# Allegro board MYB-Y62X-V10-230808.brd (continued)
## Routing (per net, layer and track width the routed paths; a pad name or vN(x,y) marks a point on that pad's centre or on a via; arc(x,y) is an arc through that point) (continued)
SOC_MCU_MCAN1_TX: length 60.2
  TOP w0.152: v2(45.44,112.07) R77.2 45.77,110.16 U47.15 ; U43.L56 76.12,89.79 v2(75.48,90.42)
  BOTTOM w0.152: v2(75.48,90.42) 75.21,90.7 70,90.7 65.4,95.3 61.79,95.3 57.91,99.19 43.61,99.19 41.07,101.73 41.07,109.73 43.41,112.07 v2(45.44,112.07)
SOC_MCU_RESETZ: length 119.8
  TOP w0.152: v2(160.07,14.99) 160.07,14.25 160.45,13.87 D44.1 ; v2(81.23,47.42) 81.23,49.76 U43.L21
  ART03 w0.152: v2(160.07,14.99) 160.07,16.89 158.92,18.03 155.11,18.03 v2(154.15,19)
  BOTTOM w0.152: C240.1 R414.2 160.83,14.22 v2(160.07,14.99) ; v2(81.23,47.42) 85.42,47.42 86.64,48.64 90.93,48.64 91.39,48.18 105.18,48.18 109.67,52.68 110.54,52.68 111.02,52.2 114.5,52.2 116.05,50.65 116.05,45.9 117.56,44.39 122.51,44.39 124.63,42.27 124.63,27.33 125.04,26.92 126.44,26.92 127.05,26.31 127.05,24.21 127.5,23.75 137.94,23.75 138.43,24.23 140.23,24.23 140.51,24.51 144.47,24.51 145.73,23.25 148.42,23.25 150.08,21.59 150.9,21.59 151.18,21.31 151.18,20.02 151.41,19.79 152.08,19.79 152.86,19 v2(154.15,19)
SOC_MCU_SPI0_CLK: length 87.6
  TOP w0.152: U18.8 158.4,70.22 158.67,70.48 R158.2 159.37,70.97 159.22,71.12 152.95,71.12 152.07,72.01 150.67,72.01 148.64,74.04 v2(143.38,74.04) ; U43.L53 v2(82.72,87.88)
  ART03 w0.152: v2(102.47,87.3) 102.42,87.25 83.36,87.25 v2(82.72,87.88)
  BOTTOM w0.152: v2(143.38,74.04) 143.38,75.16 138.27,80.26 132.71,80.26 132.3,80.67 120.16,80.67 115.41,85.42 105.61,85.42 103.73,87.3 v2(102.47,87.3)
SOC_MCU_SPI0_CS0: length 101.5
  TOP w0.152: U43.L2 68.5,84.71 v2(67.99,84.2) ; v2(119.55,83.31) 121.08,81.79 128.22,81.79 128.9,81.1 128.9,79.15 129.94,78.11 137.97,78.11 142.54,73.53 148.38,73.53 150.54,71.37 151.87,71.37 R159.2 153.03,70.22 U18.1
  ART03 w0.152: v2(67.99,84.2) 67.99,86.74 70.28,89.03 79,89.03 79.93,89.96 98.23,89.96 98.42,90.14 103.7,90.14 110.16,83.69 117.14,83.69 117.52,83.31 v2(119.55,83.31)
SOC_MCU_SPI0_D0: length 140.2
  TOP w0.152: U43.L3 66.72,82.8 v2(65.83,81.92)
  ART03 w0.152: v2(65.83,81.92) 65.22,82.52 65.22,87.68 70.89,93.34 91.61,93.34 92.63,92.33 94.53,92.33 95.14,91.72 104.8,91.72 110.79,85.72 118.16,85.72 118.66,85.22 v2(120.06,85.22)
  BOTTOM w0.152: v2(120.06,85.22) 120.06,85.06 122.42,82.7 137.82,82.7 145.21,75.31 145.21,60.12 152.41,52.92 152.41,50.71 159.18,43.94 161.59,43.94 161.78,43.76 R160.2 R148.2
SOC_MCU_SPI0_D1: length 63.4
  TOP w0.152: R127.2 v2(16.3,94.36) ; U43.L4 v2(65.83,80.26)
  ART03 w0.152: v2(50.24,89.99) 50.72,89.51 v2(50.72,81.81)
  BOTTOM w0.152: v2(65.83,80.26) 64.28,81.81 v2(50.72,81.81) ; v2(50.24,89.99) 49.95,90.28 31.61,90.28 27.53,94.36 v2(16.3,94.36)
SOC_MCU_UART0_RXD: length 77.5
  TOP w0.152: U43.L1 v2(68.5,86.23) ; R12.1 79.55,27.84 78.53,28.85 v2(69.24,28.85)
  BOTTOM w0.152: v2(68.5,86.23) 68.75,85.98 68.75,83.82 67.46,82.52 67.46,74.45 68.75,73.15 68.75,59.31 66.85,57.4 66.85,45.21 62.73,41.1 62.73,35.36 v2(69.24,28.85)
SOC_MCU_UART0_TXD: length 82.6
  TOP w0.152: v2(79.57,21.21) R562.1 ; U43.L58 69.77,87.88 69.13,87.25 v2(69.13,86.74)
  BOTTOM w0.152: v2(79.57,21.21) 77.19,21.21 72.61,25.78 71.59,25.78 62.23,35.15 62.23,41.31 66.34,45.42 66.34,57.61 68.25,59.52 68.25,72.94 66.95,74.24 66.95,83.92 67.99,84.96 67.99,86.36 68.37,86.74 v2(69.13,86.74)
SOC_MMC1_CLK: length 31.6
  TOP w0.152: J2.5 81.22,109.89 82.22,108.89 D5.2 82.19,108.09 81.56,107.46 81.56,106.2 82.09,105.66 v2(82.22,105.66) R37.2 ; U43.149 81.78,92.51 81.1,93.19 78.96,93.19 78.81,93.34 v2(78.81,94.23)
  BOTTOM w0.152: v2(82.22,105.66) 82.22,105.79 82.7,106.27 82.7,106.6 83.1,107.01 84.68,107.01 85.01,106.68 85.01,105.54 81.81,102.34 81.81,99.31 80.95,98.45 80.95,95.83 79.35,94.23 v2(78.81,94.23)
SOC_MMC1_CMD: length 32
  TOP w0.152: U43.156 v2(74.78,94.35) ; J2.3 79.02,108.11 D4.2 79.55,107.58 79.55,106.17 v2(79.04,105.66) R36.2
  BOTTOM w0.152: v2(79.04,105.66) 77.95,104.57 77.95,104.13 78.08,104 78.32,104 78.46,103.86 78.46,103.67 78.32,103.54 78.08,103.54 77.95,103.41 77.95,102.95 75.09,100.09 75.09,98.66 74.95,98.53 74.72,98.53 74.57,98.68 74.57,99.26 74.42,99.42 73.35,99.42 73.2,99.26 73.2,98.99 73.35,98.84 73.83,98.84 73.99,98.69 73.99,98.38 73.83,98.23 73.35,98.23 73.2,98.08 73.2,97.75 73.35,97.59 73.83,97.59 73.99,97.44 73.99,97.14 73.83,96.98 73.61,96.98 73.4,96.77 73.4,96.47 73.63,96.24 75.36,96.24 75.51,96.09 75.51,95.76 75.36,95.61 74.37,95.61 74.21,95.45 74.21,94.87 74.73,94.35 v2(74.78,94.35)
SOC_MMC1_DAT0: length 31.3
  TOP w0.152: v2(75.78,94.35) 75.43,94.35 75.28,94.2 75.28,93.7 75.43,93.55 75.63,93.55 75.78,93.39 U43.155 ; R38.2 v2(83.36,105.66) 83.36,105.66 82.75,106.27 82.75,107.48 D6.2 83.42,108.15 J2.7
  BOTTOM w0.152: v2(83.36,105.66) 83.36,105.49 82.17,104.29 81.46,104.29 81.3,104.44 81.3,104.98 81.15,105.13 80.85,105.13 80.69,104.98 80.69,104.44 80.54,104.29 80.01,104.29 79.6,103.89 79.6,102.64 79.45,102.49 78.1,102.49 77.89,102.27 77.89,102.06 78.04,101.9 79.52,101.9 79.63,101.8 79.63,98.09 78.13,96.6 78.13,95.38 77.87,95.12 76.88,95.12 76.11,94.35 v2(75.78,94.35)
SOC_MMC1_DAT1: length 31.8
  TOP w0.152: J2.8 84.52,108.1 D7.2 83.87,107.45 83.87,105.74 v2(83.94,105.66) 84.01,105.66 R39.2 ; v2(76.78,94.36) 76.4,94.36 76.25,94.21 76.25,93.85 76.4,93.69 77.29,93.69 77.44,93.54 77.44,93.24 77.29,93.08 76.4,93.08 76.25,92.93 76.25,92.61 76.4,92.46 76.67,92.46 76.78,92.35 U43.154
  BOTTOM w0.152: v2(76.78,94.36) 76.78,94.39 77.14,94.74 78,94.74 78.46,95.2 78.46,96.32 79.14,97 79.36,97 79.5,96.86 79.72,96.86 79.93,97.08 79.93,97.3 79.79,97.44 79.79,97.65 80.08,97.94 80.08,100.06 80.23,100.21 80.77,100.21 80.92,100.36 80.92,100.67 80.77,100.82 80.23,100.82 80.08,100.97 80.08,101.27 80.23,101.43 80.77,101.43 80.92,101.58 80.92,101.88 80.77,102.04 80.23,102.04 80.08,102.19 80.08,103.61 80.31,103.84 82.27,103.84 83.94,105.51 v2(83.94,105.66)
SOC_MMC1_DAT2: length 31.4
  TOP w0.152: R34.2 v2(76.88,105.66) 77.39,106.17 77.39,107.58 D2.2 76.82,108.15 J2.1 ; U43.158 v2(72.78,94.35)
  BOTTOM w0.152: v2(72.78,94.35) 72.6,94.35 71.93,95.02 71.93,95.61 71.78,95.76 70.51,95.76 70.25,96.01 70.25,98.35 70.1,98.5 69.39,98.5 69.24,98.65 69.24,98.93 69.39,99.08 70.13,99.08 70.28,99.23 70.28,99.54 70.13,99.69 69.39,99.69 69.24,99.84 69.24,100.2 69.4,100.37 74.23,100.37 76.88,103.02 v2(76.88,105.66)
SOC_MMC1_DAT3: length 31.8
  TOP w0.152: U43.157 v2(73.78,94.35) ; J2.2 77.92,108.2 D3.2 78.53,107.58 78.53,106.17 v2(78.02,105.66) R35.2
  BOTTOM w0.152: v2(78.02,105.66) 77.39,105.03 77.39,102.97 74.34,99.92 71.09,99.92 70.94,99.77 70.94,99.55 71.07,99.42 72.54,99.42 72.69,99.26 72.69,99 72.56,98.87 72.27,98.87 72.13,98.73 72.13,98.55 72.27,98.41 72.56,98.41 72.69,98.28 72.69,98.08 72.54,97.93 72.24,97.93 72.11,97.8 72.11,96.9 71.95,96.75 71.05,96.75 70.91,96.62 70.91,96.34 71.04,96.22 72.77,96.22 73.78,95.2 v2(73.78,94.35)
SOC_MMC1_SDCD: length 32.7
  TOP w0.152: v2(71.95,94.34) 71.78,94.16 U43.159 ; R40.2 v2(85.99,105.64) 86.08,105.73 86.08,107.53 D8.2 85.62,108.19 J2.9
  BOTTOM w0.152: v2(85.99,105.64) 85.99,105.35 82.75,102.11 82.75,98.86 81.89,97.99 81.89,95.48 79.83,93.42 78.18,93.42 77.8,93.8 72.49,93.8 v2(71.95,94.34)
SOC_MMC2_CLK: length 58.2
  TOP w0.152: U43.144 86.78,92.08 v2(86.28,92.58) ; R85.1 v2(43.78,107.52)
  BOTTOM w0.152: v2(86.28,92.58) 86.03,92.33 84.5,92.33 84.02,92.81 82.57,92.81 81.53,91.77 79.98,91.77 79.52,91.31 77.06,91.31 76.81,91.57 70.53,91.57 65.6,96.49 62.05,96.49 58.21,100.33 43.64,100.33 41.96,102.01 41.96,105.7 v2(43.78,107.52)
SOC_MMC2_CMD: length 58.3
  TOP w0.152: R84.1 v2(43.23,108.41) ; U43.147 v2(83.78,92.33)
  BOTTOM w0.152: v2(83.78,92.33) 83.78,91.4 83.61,91.24 83.2,91.24 83.05,91.39 83.05,91.67 82.9,91.82 82.59,91.82 82.44,91.67 82.44,91.34 82.29,91.19 80.11,91.19 79.8,90.88 76.78,90.88 76.55,91.11 70.35,91.11 65.57,95.9 61.86,95.9 58.06,99.69 43.74,99.69 41.58,101.85 41.58,106.76 v2(43.23,108.41)
SOC_MMC2_DAT0: length 58.3
  TOP w0.152: R78.1 v2(43.61,104.14) ; U43.146 84.78,92.81 v2(84.76,92.84)
  BOTTOM w0.152: v2(43.61,104.14) 43.2,103.73 43.2,102.56 43.81,101.96 46.94,101.96 47.85,102.87 48.79,102.87 48.94,103.02 48.94,103.35 49.09,103.5 49.39,103.5 49.55,103.35 49.55,103.02 49.7,102.87 50,102.87 50.16,103.02 50.16,103.35 50.31,103.5 50.61,103.5 50.77,103.35 50.77,103.02 50.92,102.87 51.22,102.87 51.38,103.02 51.38,103.35 51.53,103.5 51.83,103.5 51.99,103.35 51.99,103.02 52.14,102.87 52.44,102.87 52.6,103.02 52.6,103.35 52.75,103.5 53.05,103.5 53.2,103.35 53.2,103.02 53.36,102.87 53.66,102.87 53.81,103.02 53.81,103.35 53.97,103.5 54.27,103.5 54.42,103.35 54.42,103.02 54.58,102.87 54.88,102.87 55.03,103.02 55.03,103.35 55.19,103.5 55.49,103.5 55.64,103.35 55.64,103.02 55.8,102.87 56.1,102.87 56.25,103.02 56.25,103.35 56.41,103.5 56.71,103.5 56.86,103.35 56.86,103.02 57.01,102.87 57.38,102.87 57.53,103.02 57.53,103.33 57.68,103.48 57.99,103.48 58.14,103.33 58.14,103.02 58.29,102.87 61.17,102.87 71.08,92.96 77.4,92.96 77.62,92.74 80.64,92.74 81.25,93.34 84.25,93.34 v2(84.76,92.84)
SOC_MMC2_DAT1: length 58.2
  TOP w0.152: R80.1 v2(43.61,103) ; v2(85.78,93.88) U43.145
  BOTTOM w0.152: v2(43.61,103) 44.17,102.44 45.64,102.44 47.14,103.94 47.89,103.94 48.04,104.09 48.04,104.55 48.19,104.7 48.5,104.7 48.65,104.55 48.65,104.11 48.83,103.94 49.11,103.94 49.26,104.09 49.26,104.55 49.41,104.7 49.72,104.7 49.87,104.55 49.87,104.11 50.05,103.94 50.33,103.94 50.48,104.09 50.48,104.55 50.63,104.7 50.93,104.7 51.09,104.55 51.09,104.11 51.26,103.94 51.54,103.94 51.7,104.09 51.7,104.55 51.85,104.7 52.15,104.7 52.31,104.55 52.31,104.11 52.48,103.94 52.76,103.94 52.92,104.09 52.92,104.55 53.07,104.7 53.37,104.7 53.53,104.55 53.53,104.11 53.7,103.94 54.27,103.94 54.43,104.09 54.43,104.5 54.58,104.65 54.88,104.65 55.04,104.5 55.04,104.09 55.19,103.94 60.8,103.94 71.41,93.33 77.61,93.33 77.87,93.07 80.16,93.07 80.95,93.85 85.75,93.85 v2(85.78,93.88)
SOC_MMC2_DAT2: length 57.9
  TOP w0.152: R82.1 v2(43.61,105.28) ; U43.153 v2(77.78,92.25)
  BOTTOM w0.152: v2(43.61,105.28) 42.72,104.39 42.72,102.62 43.89,101.45 48.54,101.45 48.69,101.6 48.69,102.16 48.84,102.31 49.15,102.31 49.3,102.16 49.3,101.6 49.45,101.45 49.76,101.45 49.91,101.6 49.91,102.16 50.06,102.31 50.37,102.31 50.52,102.16 50.52,101.6 50.67,101.45 50.98,101.45 51.13,101.6 51.13,102.16 51.28,102.31 51.59,102.31 51.74,102.16 51.74,101.6 51.89,101.45 52.2,101.45 52.35,101.6 52.35,102.16 52.5,102.31 52.81,102.31 52.96,102.16 52.96,101.6 53.11,101.45 53.42,101.45 53.57,101.6 53.57,102.16 53.72,102.31 54.03,102.31 54.18,102.16 54.18,101.6 54.33,101.45 54.64,101.45 54.79,101.6 54.79,102.16 54.94,102.31 55.25,102.31 55.4,102.16 55.4,101.6 55.55,101.45 55.86,101.45 56.01,101.6 56.01,102.16 56.16,102.31 56.46,102.31 56.62,102.16 56.62,101.6 56.77,101.45 57.07,101.45 57.23,101.6 57.23,102.16 57.38,102.31 57.68,102.31 57.84,102.16 57.84,101.6 57.99,101.45 58.29,101.45 58.45,101.6 58.45,102.16 58.6,102.31 58.9,102.31 59.06,102.16 59.06,101.6 59.21,101.45 59.51,101.45 59.67,101.6 59.67,102.11 59.82,102.26 60.12,102.26 60.27,102.11 60.27,101.6 60.43,101.45 61.82,101.45 70.76,92.51 77.19,92.51 77.44,92.25 v2(77.78,92.25)
SOC_MMC2_DAT3: length 57.9
  TOP w0.152: R83.1 v2(43.73,106.43) ; U43.151 v2(79.78,92.3)
  BOTTOM w0.152: v2(43.73,106.43) 42.34,105.03 42.34,102.36 43.76,100.94 58.37,100.94 59.57,99.74 59.79,99.74 60.6,100.55 60.81,100.55 61.03,100.33 61.03,100.12 60.27,99.35 60.27,99.04 60.48,98.82 60.7,98.82 61.51,99.63 61.73,99.63 61.94,99.42 61.94,99.2 61.13,98.39 61.13,98.18 61.35,97.96 61.56,97.96 62.3,98.7 62.51,98.7 62.73,98.48 62.73,98.26 61.99,97.53 61.99,97.31 62.32,96.99 63.48,96.99 63.63,97.14 63.63,98.02 63.78,98.17 64.09,98.17 64.24,98.02 64.24,97.14 64.39,96.99 65.74,96.99 70.66,92.08 77.01,92.08 77.34,91.74 79.22,91.74 v2(79.78,92.3)
SOC_MMC2_SDCD: length 100.2
  TOP w0.152: U43.148 v2(82.78,92.33) ; v2(60.31,21.34) R308.2 59.74,20.57 59.38,20.22 59.38,19.66 59.12,19.4 U29.6
  ART03 w0.152: v2(66.44,78.99) 66.44,82.12 65.76,82.8 65.76,87.5 70.05,91.8 78.96,91.8 79.32,92.15 79.32,92.53 79.63,92.84 81.38,92.84 81.88,92.33 v2(82.78,92.33)
  BOTTOM w0.152: v2(66.44,78.99) 66.44,74.07 67.74,72.77 67.74,59.82 65.83,57.91 65.83,47.75 64.74,46.66 59.41,46.66 57.58,44.83 57.58,40.77 56.18,39.37 56.18,31.17 58.21,29.13 58.21,25.4 58.85,24.77 58.85,23.11 60.31,21.65 v2(60.31,21.34)
SOC_OSPI0_CLK: length 11.2
  TOP w0.152: R51.2 v2(89.84,93.83) ; v2(97.71,92.46) 97.79,92.46 98.78,91.46 U43.132
  BOTTOM w0.152: v2(89.84,93.83) 89.84,93.73 90.19,93.37 91.77,93.37 93.01,92.13 95.47,92.13 96.06,92.71 97.46,92.71 v2(97.71,92.46)
SOC_OSPI0_CSN0: length 15.9
  TOP w0.152: R54.2 v2(90.72,93.83) ; v2(102.78,93.24) U43.128
  BOTTOM w0.152: v2(90.72,93.83) 91.92,93.83 93.21,92.53 95.3,92.53 95.88,93.12 96.47,93.12 97.15,93.8 102.22,93.8 v2(102.78,93.24)
SOC_OSPI0_CSN1: length 24.4
  TOP w0.152: U43.129 101.78,93.5 103.15,94.87 108.89,94.87 113.71,90.04 119.61,90.04 120.38,90.81 R285.1
SOC_OSPI0_DQ0: length 11.1
  TOP w0.152: v2(97.2,93.22) 97.2,94.18 R52.2 ; U43.139 v2(91.78,92.46)
  BOTTOM w0.152: v2(91.78,92.46) 92.54,91.69 97.71,91.69 98.22,92.2 98.22,92.71 97.71,93.22 v2(97.2,93.22)
SOC_OSPI0_DQ1: length 4.2
  TOP w0.152: R53.2 92.5,93.68 92.38,93.55 92.05,93.55 91.89,93.4 91.89,93.07 92.05,92.91 92.63,92.91 92.78,92.76 U43.138
SOC_OSPI0_DQ2: length 9.9
  TOP w0.152: U43.137 v2(93.78,90.37) ; R55.2 v2(99.61,93.22)
  BOTTOM w0.152: v2(93.78,90.37) 98.01,90.37 99.61,91.97 v2(99.61,93.22)
SOC_OSPI0_DQ3: length 12.4
  TOP w0.152: R56.2 98.34,93.92 v2(98.34,93.22) ; U43.140 v2(90.78,92.46)
  BOTTOM w0.152: v2(90.78,92.46) 91.92,91.31 97.84,91.31 98.6,92.08 98.6,92.96 v2(98.34,93.22)
SOC_OSPI0_DQ4: length 14
  TOP w0.152: R58.2 98.98,94.18 v2(98.98,93.22) ; U43.141 v2(89.78,92.46)
  BOTTOM w0.152: v2(98.98,93.22) 98.98,91.95 97.96,90.93 91.3,90.93 v2(89.78,92.46)
SOC_OSPI0_DQ5: length 3.8
  TOP w0.152: U43.133 97.78,91.6 96.74,92.63 96.74,93.74 R59.2
SOC_OSPI0_DQ6: length 4.7
  TOP w0.152: R60.2 92.91,93.95 92.91,93.37 93.24,93.04 93.24,92.41 93.42,92.23 94.58,92.23 94.78,92.02 U43.136
SOC_OSPI0_DQ7: length 21.2
  TOP w0.152: U43.142 88.78,92.06 87.25,93.6 87.25,97.18 87.4,97.33 87.89,97.33 88.14,97.08 88.99,97.08 89.12,96.94 89.12,96.76 88.99,96.62 88.14,96.62 88.01,96.49 88.01,96.3 88.14,96.16 88.99,96.16 89.12,96.03 89.12,95.84 88.99,95.71 88.14,95.71 88.01,95.57 88.01,95.38 88.14,95.25 88.99,95.25 89.12,95.12 89.12,94.93 88.99,94.79 88.14,94.79 88.01,94.66 88.01,93.9 88.67,93.24 91.03,93.24 91.61,93.83 R61.2
SOC_OSPI0_DQS: length 11.9
  TOP w0.152: U43.135 95.78,92.48 95.6,92.66 93.77,92.66 93.65,92.79 93.65,93.01 93.8,93.17 94.81,93.17 94.97,93.32 v2(94.97,93.7) 94.97,94.23 R63.1
  BOTTOM w0.152: v2(94.97,93.7) 94.97,93.55 94.81,93.4 93.55,93.4 93.4,93.24 93.4,93.06 93.52,92.94 95.12,92.94 95.58,93.4 95.58,94.02 R63.1
SOC_OSPI0_ECC_FAIL: length 3.4
  TOP w0.152: R57.2 100.15,94.07 100.15,92.74 99.78,92.37 U43.131
SOC_OSPI0_LBCLK: length 13.2
  TOP w0.152: U43.127 103.78,92.91 v2(102.82,93.88) ; v2(95.8,96.98) 95.8,96.82 95.17,96.19 R63.2
  BOTTOM w0.152: v2(95.8,96.98) 99.72,96.98 v2(102.82,93.88)
SOC_OSPI0_RESETOUT1: length 26.7
  TOP w0.152: U43.130 v2(100.78,92.31) ; v2(97.33,111.45) U8.1
  BOTTOM w0.152: v2(97.33,111.45) 97.89,110.89 97.89,102.44 99.87,100.46 99.87,97.66 103.35,94.18 103.35,93.17 102.49,92.31 v2(100.78,92.31)
SOC_PORZ_OUT: length 20.8
  TOP w0.152: v2(72.54,47.73) 74.06,47.73 U43.L19 ; U35.2 v2(70.74,38.1) 66.87,38.1 U39.2
  BOTTOM w0.152: v2(70.74,38.1) 70.74,45.92 v2(72.54,47.73)
SOC_RESET_REQZ: length 126.4
  TOP w0.152: D46.1 160.93,21.74 v2(160.7,21.97) ; U43.L17 v2(71.04,47.37)
  BOTTOM w0.152: C242.1 R416.2 v2(160.7,21.97) 155.52,16.79 151.84,16.79 149.75,18.87 149.2,18.87 148.43,19.63 148.43,21.31 147.77,21.97 144.45,21.97 143.81,22.61 140.89,22.61 140.51,22.23 133.04,22.23 131.92,23.34 126.79,23.34 126.67,23.47 78.84,23.47 76.22,26.09 76.22,26.77 72.06,30.94 72.06,34.67 71.04,35.69 67.53,35.69 67.23,35.99 67.23,37.59 67.86,38.23 69.64,38.23 70.15,38.73 70.15,46.48 v2(71.04,47.37)
SOC_RESETSTATZ: length 159.5
  TOP w0.152: U43.L18 v2(74.47,49.78) ; U8.2 v2(96.69,112.39)
  ART03 w0.152: v2(113.46,80.64) 113.97,80.14 122.6,80.14 125.28,77.46 127.54,77.46 129.03,78.94 129.03,87.78 131.57,90.32 134.13,90.32 v2(134.81,91) ; v2(105.71,80.26) 103.96,78.51 103.96,72.54 104.57,71.93 104.57,51.18 102.03,48.64 92.2,48.64 91.06,49.78 78.28,49.78 77.77,49.28 74.98,49.28 v2(74.47,49.78)
  BOTTOM w0.152: v2(96.69,112.39) 97.46,112.39 98.47,111.38 98.47,102.87 100.38,100.97 100.38,97.92 102.92,95.38 130.43,95.38 v2(134.81,91) ; v2(105.71,80.26) 106.09,80.64 v2(113.46,80.64)
SOC_RGMII1_RD0: length 13.9
  TOP w0.152: R358.2 92.79,39.43 v2(92.79,39.98) ; U43.72 v2(95.78,45.21)
  BOTTOM w0.152: v2(92.79,39.98) 92.79,41.33 92.64,41.48 92.07,41.48 91.92,41.63 91.92,41.94 92.07,42.09 92.64,42.09 92.79,42.24 92.79,42.55 92.64,42.7 92.07,42.7 91.92,42.85 91.92,43.16 92.07,43.31 92.64,43.31 92.79,43.46 92.79,44.41 93.6,45.21 94.39,45.21 94.54,45.36 94.54,46 94.7,46.15 95,46.15 95.15,46 95.15,45.36 95.31,45.21 v2(95.78,45.21)
SOC_RGMII1_RD0_R: length 5.2
  TOP w0.152: R358.1 v2(92.92,37.72) 91.67,36.47 U33.26
  BOTTOM w0.152: v2(92.92,37.72) R358.1 R372.1
SOC_RGMII1_RD1: length 13.4
  TOP w0.152: U43.73 v2(96.78,45.21) ; R356.2 v2(93.94,40.26)
  BOTTOM w0.152: v2(96.78,45.21) 96.78,44.64 96.62,44.48 93.57,44.48 93.24,44.15 93.24,42.84 93.39,42.69 94.26,42.69 94.41,42.54 94.41,42.24 94.26,42.08 93.39,42.08 93.24,41.93 93.24,41.63 93.39,41.47 94.26,41.47 94.41,41.32 94.41,40.73 v2(93.94,40.26)
SOC_RGMII1_RD1_R: length 5.2
  TOP w0.152: U33.25 92.07,35.73 93.94,37.59 v2(93.94,37.72) R356.1
  BOTTOM w0.152: R376.1 94.7,37.97 94.45,37.72 v2(93.94,37.72)
SOC_RGMII1_RD2: length 13.4
  TOP w0.152: v2(94.92,43.94) 91.49,43.94 90.78,44.65 U43.67 ; R357.2 v2(96.16,39.37)
  BOTTOM w0.152: v2(96.16,39.37) 95.52,40.01 95.52,40.37 94.92,40.97 v2(94.92,43.94)
SOC_RGMII1_RD2_R: length 4.7
  TOP w0.152: R357.1 v2(94.7,37.18) 93.4,35.89 93.4,34.77 93.19,34.56 U33.24
  BOTTOM w0.152: R357.1 v2(94.7,37.18)
SOC_RGMII1_RD3: length 13.8
  TOP w0.152: v2(95.68,43.94) 94.78,44.84 U43.71 ; v2(96.19,40.01) 96.69,39.5 96.69,36.83 R359.2
  BOTTOM w0.152: v2(96.19,40.01) 96.19,40.51 95.68,41.02 95.68,41.33 95.83,41.48 96.39,41.48 96.54,41.63 96.54,41.94 96.39,42.09 95.83,42.09 95.68,42.24 95.68,42.55 95.83,42.7 96.39,42.7 96.54,42.85 96.54,43.16 96.39,43.31 95.83,43.31 95.68,43.46 v2(95.68,43.94)
SOC_RGMII1_RD3_R: length 4.4
  TOP w0.152: U33.23 93.42,34.16 93.91,34.65 93.91,35.53 v2(94.67,36.29) R359.1
  BOTTOM w0.152: R359.1 v2(94.67,36.29)
SOC_RGMII1_RX_CTL: length 14.4
  TOP w0.152: v2(92.12,45.09) 91.78,45.43 U43.68 ; R355.2 91.91,39.71 91.72,39.9 v2(91.52,39.9)
  BOTTOM w0.152: v2(91.52,39.9) 91.52,43.37 91.37,43.52 90.95,43.52 90.79,43.37 90.79,42.88 90.64,42.72 90.34,42.72 90.18,42.88 90.18,43.57 90.03,43.72 88.74,43.72 88.59,43.88 88.59,44.18 88.74,44.33 91.37,44.33 91.52,44.49 91.52,44.49 v2(92.12,45.09)
SOC_RGMII1_RXC: length 14.4
  TOP w0.152: R354.2 v2(90.89,39.9) ; U43.70 93.78,44.94 93.34,44.5 91.69,44.5 v2(91.23,44.96)
  BOTTOM w0.152: v2(90.89,39.9) 90.89,41.59 89.86,42.62 88.95,42.62 88.16,43.41 88.16,44.37 88.74,44.96 v2(91.23,44.96)
SOC_RGMII1_RXC_R: length 4.9
  TOP w0.152: U33.28 90.89,35.37 v2(90.89,37.72) R354.1
  BOTTOM w0.152: R374.1 R369.2 90.89,37.79 v2(90.89,37.72)
SOC_RGMII1_RXCTL_R: length 5
  TOP w0.152: U33.27 91.27,37.09 v2(91.91,37.72) R355.1
  BOTTOM w0.152: R368.2 R375.1 92.03,37.85 v2(91.91,37.72)
SOC_RGMII1_TD0: length 25
  TOP w0.152: R352.2 v2(98.35,33.63) ; U43.65 88.78,45 90.72,43.05 98.4,43.05 99.36,42.09 v2(99.36,38.23)
  BOTTOM w0.152: v2(99.36,38.23) 99.41,38.18 99.41,34.62 99.29,34.49 99.29,34.28 99.46,34.1 99.46,33.88 99.25,33.67 99.03,33.67 98.85,33.85 98.64,33.85 98.42,33.63 v2(98.35,33.63)
SOC_RGMII1_TD0_R: length 2.8
  TOP w0.152: U33.19 94.21,32.56 R352.1
SOC_RGMII1_TD1: length 25.4
  TOP w0.152: R350.2 v2(98.35,32.74) ; U43.66 89.78,44.76 91.11,43.43 98.65,43.43 99.87,42.21 v2(99.87,38.86)
  BOTTOM w0.152: v2(98.35,32.74) 99.03,32.74 99.87,33.58 v2(99.87,38.86)
SOC_RGMII1_TD1_R: length 2.6
  TOP w0.152: U33.18 94.69,32.16 R350.1
SOC_RGMII1_TD2: length 25.3
  TOP w0.152: U43.61 84.78,45.47 85.5,44.74 85.5,44.46 85.8,44.17 86.08,44.17 86.37,43.88 86.37,43.6 86.66,43.31 86.94,43.31 87.23,43.02 87.23,42.74 87.52,42.45 87.8,42.45 88.72,41.53 95.42,41.53 97.33,39.62 v2(97.33,38.23) ; R351.2 v2(97.21,31.85)
  BOTTOM w0.152: v2(97.21,31.85) 97.13,31.93 97.13,38.02 v2(97.33,38.23)
SOC_RGMII1_TD2_R: length 2.4
  TOP w0.152: R351.1 95.18,31.76 U33.17
SOC_RGMII1_TD3: length 25.3
  TOP w0.152: v2(97.84,38.86) 97.84,39.88 95.8,41.91 89.46,41.91 85.78,45.59 U43.62 ; R353.2 96.59,31.39 97.41,31.39 v2(97.84,31.83)
  BOTTOM w0.152: v2(97.84,38.86) v2(97.84,31.83)
SOC_RGMII1_TD3_R: length 2.6
  TOP w0.152: U33.16 93.82,31.36 94.22,30.96 R353.1
SOC_RGMII1_TX_CTL: length 24.4
  TOP w0.152: v2(98.85,38.86) 98.85,41.88 98.07,42.67 97.71,42.67 97.56,42.52 97.56,42.19 97.41,42.04 97.1,42.04 96.95,42.19 96.95,42.52 96.8,42.67 90.45,42.67 87.78,45.34 U43.64 ; R349.2 v2(98.35,34.52)
  BOTTOM w0.152: v2(98.85,38.86) 98.85,34.67 98.7,34.52 v2(98.35,34.52)
SOC_RGMII1_TXC: length 23.9
  TOP w0.152: R348.2 96.87,35.4 97.03,35.56 97.03,35.84 97.18,35.99 97.48,35.99 97.64,35.84 97.64,35.56 97.79,35.4 v2(98.35,35.4) ; v2(98.35,38.23) 98.35,40.06 97.79,40.62 97.79,40.84 98.24,41.29 98.24,41.51 98.03,41.72 97.81,41.72 97.36,41.27 97.14,41.27 96.12,42.29 89.86,42.29 86.78,45.37 U43.63
  BOTTOM w0.152: v2(98.35,38.23) v2(98.35,35.4)
SOC_RGMII1_TXC_R: length 4.1
  TOP w0.152: U33.21 94.02,33.36 94.32,33.66 94.32,35.09 94.63,35.4 R348.1
SOC_RGMII1_TXCTL_R: length 3.3
  TOP w0.152: R349.1 94.7,33.94 94.7,33.53 94.13,32.96 U33.20
SOC_RGMII2_RD0: length 21.6
  TOP w0.152: R391.2 116.51,39.85 116.51,41.02 114.22,43.31 113.38,43.31 113.21,43.48 113.21,44.35 113.06,44.5 112.76,44.5 112.6,44.35 112.6,43.48 112.4,43.28 111.71,43.28 111.25,43.74 111.25,43.96 112.02,44.73 112.02,44.95 111.81,45.16 111.59,45.16 110.83,44.4 110.59,44.4 v2(110.28,44.7) ; v2(105.78,45.09) U43.82
  BOTTOM w0.152: v2(105.78,45.09) 106.16,44.7 106.55,44.7 106.71,44.86 106.71,45.11 106.86,45.26 107.16,45.26 107.32,45.11 107.32,44.86 107.47,44.7 107.77,44.7 107.92,44.86 107.92,45.11 108.08,45.26 108.38,45.26 108.53,45.11 108.53,44.86 108.69,44.7 v2(110.28,44.7)
SOC_RGMII2_RD0_R: length 5.2
  TOP w0.152: R391.1 v2(115.96,37.59) 115.96,36.83 114.97,35.84 U37.26
  BOTTOM w0.152: v2(115.96,37.59) R391.1 R407.1
SOC_RGMII2_RD1: length 21.3
  TOP w0.152: v2(113.58,44.58) 117.01,41.15 117.01,39.47 R392.2 ; v2(106.22,47.5) 106.22,50.55 107.01,51.33 U43.86
  BOTTOM w0.152: v2(106.22,47.5) 108.25,47.5 108.66,47.09 108.66,46.87 108.38,46.6 108.38,46.38 108.57,46.19 108.84,46.19 109.09,46.44 109.31,46.44 111.17,44.58 v2(113.58,44.58)
SOC_RGMII2_RD1_R: length 5.3
  TOP w0.152: R392.1 v2(116.85,37.59) 116.85,37.08 115.37,35.6 U37.25
  BOTTOM w0.152: R411.1 117.74,37.85 117.48,37.59 v2(116.85,37.59)
SOC_RGMII2_RD2: length 21
  TOP w0.152: R393.2 119.45,37.37 117.52,39.29 117.52,41.4 v2(114.16,44.77) ; U43.85 v2(109.11,50.33)
  BOTTOM w0.152: v2(109.11,50.33) 108.89,50.33 108.38,49.83 108.38,48.01 111.3,45.09 113.84,45.09 v2(114.16,44.77)
SOC_RGMII2_RD2_R: length 4.8
  TOP w0.152: U37.24 116.61,34.56 117.23,35.18 117.23,36.42 v2(117.99,37.18) R393.1
  BOTTOM w0.152: R393.1 v2(117.99,37.18)
SOC_RGMII2_RD3: length 21.2
  TOP w0.152: v2(114.22,45.47) 118.66,41.02 118.66,39.88 120.37,38.18 120.37,36.55 120.11,36.29 R394.2 ; U43.84 v2(108.89,49.33)
  BOTTOM w0.152: v2(114.22,45.47) 111.55,45.47 108.89,48.13 v2(108.89,49.33)
SOC_RGMII2_RD3_R: length 4.4
  TOP w0.152: R394.1 v2(117.96,36.29) 117.61,35.94 117.61,35.05 116.72,34.16 U37.23
  BOTTOM w0.152: R394.1 v2(117.96,36.29)
SOC_RGMII2_RX_CTL: length 21.7
  TOP w0.152: v2(106.73,46.99) 106.73,48.13 106.93,48.33 U43.83 ; R390.2 115.24,39.47 115.24,41.55 113.97,42.82 111.17,42.82 109.65,44.35 v2(109.65,45.21)
  BOTTOM w0.152: v2(109.65,45.21) 109.59,45.21 109.16,45.64 108.16,45.64 108.01,45.8 108.01,46.05 107.86,46.2 107.55,46.2 107.4,46.05 107.4,45.8 107.25,45.64 106.94,45.64 106.79,45.8 106.79,46.13 106.64,46.28 106.33,46.28 106.18,46.13 106.18,45.9 106.03,45.75 104.97,45.75 104.77,45.95 104.77,46.69 105.08,46.99 v2(106.73,46.99)
SOC_RGMII2_RXC: length 22
  TOP w0.152: v2(108.12,44.2) 108.89,44.2 110.71,42.37 111.5,42.37 111.65,42.21 111.65,41.33 111.8,41.17 112.11,41.17 112.26,41.33 112.26,42.21 112.41,42.37 112.69,42.37 112.84,42.21 112.84,41.3 113,41.15 113.3,41.15 113.45,41.3 113.45,42.06 113.61,42.21 114.03,42.21 114.18,42.06 114.18,41.67 114.34,41.52 114.6,41.52 114.75,41.37 114.75,41.06 114.6,40.91 114.34,40.91 114.18,40.76 R389.2 ; U43.81 v2(104.78,44.66)
  BOTTOM w0.152: v2(108.12,44.2) 106.35,44.2 106.14,43.99 103.93,43.99 103.78,44.15 103.78,44.53 103.92,44.66 v2(104.78,44.66)
SOC_RGMII2_RXC_R: length 5.2
  TOP w0.152: R389.1 114.17,38.41 v2(114.17,37.59) U37.28
  BOTTOM w0.152: v2(114.17,37.59) 114.12,37.59 R404.2 R409.1
SOC_RGMII2_RXCTL_R: length 5
  TOP w0.152: R390.1 v2(115.07,37.59) 115.07,36.45 114.57,35.94 U37.27
  BOTTOM w0.152: R403.2 R390.1 v2(115.07,37.59)
SOC_RGMII2_TD0: length 36.5
  TOP w0.152: U43.75 98.78,44.78 101.66,41.9 v2(106.98,41.9) ; v2(120.71,33.64) 120.7,33.63 R383.2
  BOTTOM w0.152: v2(120.71,33.64) 120.71,36.11 121.28,36.68 121.28,37.15 121.13,37.3 120.9,37.3 120.75,37.45 120.75,37.76 120.9,37.91 121.13,37.91 121.28,38.06 121.28,38.37 121.13,38.52 120.9,38.52 120.75,38.67 120.75,38.98 120.9,39.13 121.13,39.13 121.28,39.28 121.28,39.59 121.13,39.74 120.9,39.74 120.75,39.89 120.75,40.2 120.9,40.35 121.13,40.35 121.28,40.5 121.28,40.82 120.72,41.38 118.31,41.38 117.78,41.9 v2(106.98,41.9)
SOC_RGMII2_TD0_R: length 2.8
  TOP w0.152: R383.1 117.5,32.56 U37.19
SOC_RGMII2_TD1: length 36.7
  TOP w0.152: v2(110.03,42.35) 101.84,42.35 99.78,44.41 U43.76 ; R388.2 v2(120.7,32.74)
  BOTTOM w0.152: v2(110.03,42.35) 118.97,42.35 119.12,42.2 119.12,41.88 119.28,41.73 119.58,41.73 119.73,41.88 119.73,42.2 119.89,42.35 120.99,42.35 121.97,41.38 121.97,36.65 121.2,35.89 121.2,33.25 v2(120.7,32.74)
SOC_RGMII2_TD1_R: length 2.6
  TOP w0.152: U37.18 117.99,32.16 R388.1
SOC_RGMII2_TD2: length 37.2
  TOP w0.152: U43.80 103.78,44.6 104.69,43.69 v2(106.98,43.69) ; R384.2 v2(121.52,31.85)
  BOTTOM w0.152: v2(106.98,43.69) 122.45,43.69 123.41,42.72 123.41,39.62 124.08,38.96 124.08,33.81 123.72,33.45 122.45,33.45 121.59,32.59 121.59,31.91 v2(121.52,31.85)
SOC_RGMII2_TD2_R: length 2.4
  TOP w0.152: R384.1 118.48,31.76 U37.17
SOC_RGMII2_TD3: length 36.8
  TOP w0.152: U43.74 97.78,45.14 101.47,41.45 v2(107.87,41.45) ; R385.2 v2(121.59,30.96)
  BOTTOM w0.152: v2(107.87,41.45) 117.6,41.45 120.19,38.86 120.19,32.36 v2(121.59,30.96)
SOC_RGMII2_TD3_R: length 2.6
  TOP w0.152: U37.16 117.12,31.36 117.51,30.96 R385.1
SOC_RGMII2_TX_CTL: length 36.2
  TOP w0.152: R387.2 v2(121.65,34.52) ; U43.77 100.78,44.71 102.15,43.33 v2(103.5,43.33)
  BOTTOM w0.152: v2(121.65,34.52) 121.65,35.65 121.87,35.86 122.4,35.86 122.55,35.71 122.55,35.58 122.7,35.43 122.98,35.43 123.14,35.59 123.14,38.18 122.42,38.89 122.42,41.83 121.46,42.8 104.03,42.8 v2(103.5,43.33)
SOC_RGMII2_TXC: length 35.9
  TOP w0.152: R386.2 v2(122.09,35.4) ; v2(109.01,43.26) 104.36,43.26 102.78,44.84 U43.79
  BOTTOM w0.152: v2(109.01,43.26) 121.86,43.26 122.88,42.24 122.88,39.37 123.59,38.66 123.59,34.57 123.29,34.26 122.37,34.26 122.09,34.54 v2(122.09,35.4)
SOC_RGMII2_TXC_R: length 3.7
  TOP w0.152: U37.21 117.31,33.36 117.61,33.66 117.61,34.45 R386.1
SOC_RGMII2_TXCTL_R: length 3.3
  TOP w0.152: U37.20 117.42,32.96 117.99,33.53 117.99,33.94 R387.1
SOC_RGMII_MDC: length 59.1
  TOP w0.152: R381.2 118.02,29.18 v2(116.97,30.23) 116.65,30.56 U37.14 ; U43.L23 88.31,47.75 v2(88.31,47.14)
  ART03 w0.152: v2(116.97,30.23) 116.97,30.24 116.68,30.53 110,30.53 109.37,31.17 99.37,31.17 v2(97.67,29.46)
  BOTTOM w0.152: R542.1 96.44,29.46 v2(97.67,29.46) 99.11,29.46 100.76,31.11 100.76,43.81 97.53,47.04 90.39,47.04 89.86,47.57 88.74,47.57 v2(88.31,47.14)
SOC_RGMII_MDIO: length 56.3
  TOP w0.152: R382.2 117.96,30.07 v2(117.52,30.51) 117.33,30.51 116.88,30.96 U37.15 ; U43.L24 88.82,47.62 v2(89.35,47.09)
  ART03 w0.152: v2(97.67,30.35) 99.83,32.51 109.32,32.51 110.05,31.78 116.06,31.78 117.33,30.51 v2(117.52,30.51)
  BOTTOM w0.152: R543.1 96.44,30.35 v2(97.67,30.35) 98.85,30.35 100.38,31.88 100.38,43.43 97.18,46.63 89.81,46.63 v2(89.35,47.09)
SOC_SPI0_CLK: length 104.6
  TOP w0.152: v2(89.07,90.42) 88.82,90.17 U43.L51
  ART03 w0.152: v2(87.86,98.04) 89.02,99.2 89.02,102.18 88.39,102.82 83,102.82 81.43,101.24 73.5,101.24 72.97,100.71 70.25,100.71 69.77,100.23 67.86,100.23 65.55,97.92 57.98,97.92 55.6,95.53 v2(55.6,91.87)
  BOTTOM w0.152: v2(89.07,90.42) 89.2,90.55 89.2,91.69 87.86,93.03 v2(87.86,98.04) ; v2(55.6,91.87) 55.67,91.8 55.67,91.01 55.47,90.81 31.92,90.81 27.86,94.87 10.7,94.87 J7.3
SOC_SPI0_CS0: length 125.7
  TOP w0.152: v2(90.22,90.42) 90.22,89.03 U43.L50
  ART03 w0.152: v2(90.72,98.63) 90.72,99.67 94.79,103.73 94.79,106.93 94.03,107.7 86.03,107.7 85.39,107.06 79.29,107.06 78.91,107.44 54.66,107.44 47.09,99.87 33.4,99.87 25.55,92.02 25.55,80.77 21.46,76.68 21.46,73 v2(22.36,72.1)
  BOTTOM w0.152: v2(90.22,90.42) 90.22,91.36 88.44,93.14 88.44,97.38 89.68,98.63 v2(90.72,98.63) ; R138.1 R136.2 20.75,72.1 v2(22.36,72.1)
SOC_SPI0_CS1: length 152.4
  TOP w0.152: U43.L44 v2(104.06,84.15)
  ART03 w0.152: v2(21.2,42.7) 18.08,45.81 18.08,51.54 16.76,52.86 16.76,61.04 13.53,64.26 13.53,82.25 16.87,85.59 17.56,85.59 21.31,89.33 21.31,93.32 v2(21.81,93.83) ; v2(87.6,87.88) 87.12,88.37 81.48,88.37 80.41,87.3 74.37,87.3 73.53,88.14 v2(72.06,88.14)
  BOTTOM w0.152: v2(104.06,84.15) 104.06,85.72 102.94,86.84 102.23,86.84 100.94,88.14 100.38,88.14 99.49,87.25 88.24,87.25 v2(87.6,87.88) ; v2(21.2,42.7) R135.2 R137.1 ; v2(21.81,93.83) 27.32,93.83 31.38,89.77 49.74,89.77 50.03,89.48 54.19,89.48 57.57,86.11 63.93,86.11 66.47,88.65 71.55,88.65 v2(72.06,88.14)
SOC_SPI0_D0: length 132.4
  TOP w0.152: U43.L52 v2(85.26,87.88)
  ART03 w0.152: v2(20.77,93.34) 20.77,89.48 17.34,86.06 16.48,86.06 12.95,82.52 12.95,64.02 16.18,60.79 16.18,52.62 17.5,51.29 17.5,44.2 21.2,40.5 v2(21.2,40.41)
  BOTTOM w0.152: v2(85.26,87.88) 83.41,87.88 82.95,87.43 71.8,87.43 71.04,88.19 66.65,88.19 64.05,85.6 57.37,85.6 53.97,89 49.81,89 49.54,89.27 31.2,89.27 27.12,93.34 v2(20.77,93.34) ; v2(21.2,40.41) R133.2 R139.1
SOC_SPI0_D1: length 133.6
  TOP w0.152: v2(107.49,93.07) 106.47,92.05 106.47,90.3 U43.L45
  ART03 w0.152: v2(107.49,93.07) 104.39,96.16 102.79,96.16 97.74,101.22 96.8,101.22 96.39,101.63 96.39,106.22 94.41,108.2 80.82,108.2 80.53,108.5 74.3,108.5 73.85,108.05 54.48,108.05 46.89,100.46 33.25,100.46 24.59,91.8 24.59,80.51 20.96,76.89 20.96,72.56 22.3,71.22 v2(22.37,71.22)
  BOTTOM w0.152: v2(22.37,71.22) 22.37,69.98 22.02,69.62 19.99,69.62 19.8,69.81 R134.2 R140.1
SOC_UART0_CTSN: length 138.8
  TOP w0.152: v2(110.53,90.44) 109.42,89.33 U43.124
  ART03 w0.152: v2(21.79,65.79) 21.89,65.89 21.89,70.99 20.57,72.31 20.57,77.25 24.05,80.73 24.05,92.02 33.07,101.04 46.65,101.04 54.2,108.58 73.45,108.58 75.42,110.55 83.17,110.55 84.63,109.09 94.43,109.09 96.9,106.63 96.9,102.97 97.1,102.77 97.71,102.77 103.73,96.75 105.46,96.75 108.66,93.55 110.06,93.55 110.53,93.08 v2(110.53,90.44)
  BOTTOM w0.152: v2(21.79,65.79) 21.31,65.79 R554.1
SOC_UART0_RTSN: length 306.2
  TOP w0.152: U43.123 110.87,88.33 v2(111.07,88.14) 111.81,88.14 115.49,84.45 115.49,79.76 v2(118.79,76.45) ; R493.1 v2(134.16,70.36) ; R494.1 v2(58.66,22.61)
  ART03 w0.152: v2(147.7,48.21) 146.99,47.5 146.3,47.5 141.33,42.53 141.33,22.92 140.79,22.38 140.79,21.36 139.49,20.07 126.49,20.07 125.88,20.68 123.47,20.68 120.14,24 81.38,24 79.8,25.58 78.46,25.58 77.52,24.64 69.97,24.64 69.11,23.77 67.97,23.77 67.1,24.64 60.75,24.64 60.18,24.07 59.29,24.07 58.85,23.62 58.85,22.8 v2(58.66,22.61) ; v2(63.42,85.09) 64.18,85.85 64.18,88.25 69.24,93.32 69.24,95.33 70.51,96.6 76.25,96.6 77.34,97.69 79.57,97.69 81.07,99.19 85.97,99.19 87.93,97.23 90.19,97.23 90.7,97.74 99.59,97.74 102.43,94.89 104.31,94.89 v2(111.07,88.14)
  BOTTOM w0.152: v2(118.79,76.45) 119.3,76.96 124.1,76.96 126.51,74.55 130.86,74.55 134.16,71.25 v2(134.16,70.36) 141.97,62.55 141.97,54.64 143.39,53.21 144.53,53.21 147.65,50.1 147.65,48.26 v2(147.7,48.21) ; v2(63.42,85.09) 50.03,85.09 46.78,81.84 46.78,74.07 45.54,72.82 27.02,72.82 21.94,67.74 19.33,67.74 R492.1
SOC_UART0_RXD: length 188.3
  TOP w0.152: R560.1 66.44,28.04 66.11,27.71 66.11,22.94 66.47,22.58 66.47,20.85 v2(67.66,19.66) ; U43.125 105.78,92.35 106.96,93.52 108.07,93.52 116.12,85.47 116.12,79.88 v2(119.55,76.45)
  ART03 w0.152: v2(146.99,46.1) 142.67,41.78 142.67,21.34 140,18.67 123.74,18.67 119.93,22.48 77.03,22.48 76.35,21.79 69.8,21.79 v2(67.66,19.66)
  BOTTOM w0.152: v2(146.99,46.1) 146.78,46.1 145.92,46.96 145.92,47.68 145.54,48.06 145.54,50.62 145.06,51.1 144.22,51.1 140.72,54.6 140.72,62.49 133.02,70.19 133.02,70.87 130.43,73.46 125.85,73.46 123.36,75.95 120.06,75.95 v2(119.55,76.45)
SOC_UART0_TXD: length 180.1
  TOP w0.152: v2(120.44,76.45) 116.76,80.14 116.76,85.5 108.33,93.93 106.45,93.93 104.78,92.26 U43.126 ; R5.1 73.25,28.04 73.71,27.58 v2(73.71,22.91)
  ART03 w0.152: v2(148.38,47.5) 147.49,46.61 146.87,46.61 142.23,41.97 142.23,21.53 139.82,19.13 123.82,19.13 119.96,22.99 73.78,22.99 v2(73.71,22.91)
  BOTTOM w0.152: v2(120.44,76.45) 123.72,76.45 126.16,74.02 130.63,74.02 133.65,70.99 133.65,70.23 141.31,62.57 141.31,54.72 144.62,51.41 145.61,51.41 147.16,49.86 147.16,47.83 147.49,47.5 v2(148.38,47.5)
SOC_UART1_CTSN: length 74.2
  TOP w0.152: U47.42 v2(62.78,105.66) ; v2(65.96,60.07) 68.37,60.07 U43.L12
  ART03 w0.152: v2(62.78,105.66) 55.8,105.66 45.51,95.38 45.51,92.23 49.25,88.49 49.25,80.98 v2(49.7,80.52)
  BOTTOM w0.152: v2(65.96,60.07) 66.72,60.83 66.72,68.27 65.35,69.64 65.35,72.11 63.64,73.82 62.69,73.82 56.5,80.01 50.21,80.01 v2(49.7,80.52)
SOC_UART1_DCDN: length 139.6
  TOP w0.152: v2(156.36,44.88) 156.36,42.38 R142.1 ; U43.L5 v2(65.83,77.72)
  ART03 w0.152: v2(65.83,77.72) 67,78.89 67,82.37 66.34,83.03 66.34,87.29 70.35,91.29 79.1,91.29 79.65,91.85 86.31,91.85 87.17,92.71 88.18,92.71 88.95,91.95 94.28,91.95 94.92,91.31 104.57,91.31 110.79,85.09 v2(118.03,85.09)
  BOTTOM w0.152: v2(156.36,44.88) 156.36,46.1 151.79,50.67 151.79,52.73 144.57,59.94 144.57,75.01 137.36,82.22 121.41,82.22 118.54,85.09 v2(118.03,85.09)
SOC_UART1_DSRN: length 226.4
  TOP w0.152: U43.L6 v2(68.5,74.17) ; R489.1 156.71,39.38 v2(156.71,40.01) ; v2(142.79,74.55) R444.1 151.88,75.03 152.16,75.31 155.75,75.31 v2(156.38,74.68) ; v2(64.79,47.42) 63.95,46.58 63.95,35.71 63.32,35.08 50.62,35.08 46.15,30.61 46.15,28.25 R291.1
  ART03 w0.152: v2(156.71,40.01) 164.28,40.01 166.52,42.24 168.5,42.24 170.23,43.97 170.23,66.55 163.5,73.28 157.78,73.28 v2(156.38,74.68) ; v2(64.79,47.42) 66.44,49.07 66.44,64.24 68.5,66.29 v2(68.5,74.17) 68.5,85.22 70.13,86.84 102.94,86.84 104.57,85.22 v2(104.57,84.58)
  BOTTOM w0.152: v2(142.79,74.55) 137.59,79.76 132.48,79.76 132.13,80.11 119.93,80.11 115.13,84.91 104.9,84.91 v2(104.57,84.58)
SOC_UART1_DTRN: length 115
  TOP w0.152: R260.1 v2(146.28,88.77) ; U43.L10 v2(65.71,65.02)
  ART03 w0.152: v2(123.87,88.77) 123.87,87.63 120.06,83.82 117.78,83.82 117.39,84.2 110.41,84.2 104.06,90.55 94.41,90.55 94.05,90.91 87.14,90.91 87.07,90.83 79.98,90.83 78.77,89.62 70.11,89.62 67.36,86.87 67.36,83.62 67.99,82.98 67.99,67.31 v2(65.71,65.02)
  BOTTOM w0.152: v2(123.87,88.77) v2(146.28,88.77)
SOC_UART1_RIN: length 110.3
  TOP w0.152: R263.1 v2(143.74,89.28) ; U43.L9 v2(65.71,67.56)
  ART03 w0.152: v2(123.24,89.28) 123.24,87.63 119.93,84.33 118.03,84.33 117.65,84.71 110.54,84.71 104.31,90.93 94.66,90.93 94.15,91.44 87.04,91.44 86.94,91.34 79.8,91.34 79.3,90.83 70.6,90.83 66.85,87.08 66.85,83.34 67.48,82.7 67.48,69.34 v2(65.71,67.56)
  BOTTOM w0.152: v2(123.24,89.28) v2(143.74,89.28)
SOC_UART1_RTSN: length 75
  TOP w0.152: U43.L11 v2(65.83,62.48) ; U47.43 62.82,106.56 v2(63.65,105.74)
  ART03 w0.152: v2(48.94,80.54) 48.94,88.01 44.88,92.08 44.88,95.61 55.44,106.17 63.22,106.17 v2(63.65,105.74)
  BOTTOM w0.152: v2(65.83,62.48) 66.21,62.87 66.21,67.99 64.87,69.33 64.87,71.96 63.42,73.41 62.32,73.41 56.22,79.5 49.98,79.5 v2(48.94,80.54)
SOC_UART1_RXD: length 60.5
  TOP w0.152: R81.1 v2(65.53,103.84) ; U43.L7 v2(65.71,72.64)
  ART03 w0.152: v2(65.53,103.84) 55.45,103.84 46.53,94.92 46.53,92.84 50.24,89.13 50.24,81.03 v2(50.75,80.52)
  BOTTOM w0.152: v2(50.75,80.52) 56.82,80.52 63.17,74.17 64.18,74.17 v2(65.71,72.64)
SOC_UART1_TXD: length 65.2
  TOP w0.152: U43.L8 v2(65.83,70.1) ; R79.1 v2(65.53,104.86)
  ART03 w0.152: v2(65.53,104.86) 55.73,104.86 46.02,95.15 46.02,92.46 49.73,88.75 v2(49.73,81.15)
  BOTTOM w0.152: v2(65.83,70.1) 66.21,70.48 66.21,72.9 64.44,74.68 63.42,74.68 56.94,81.15 v2(49.73,81.15)
SOC_UART4_RXD: length 85.9
  TOP w0.152: U43.L25 v2(92.38,49.78) ; R283.1 v2(118.6,90.81)
  ART03 w0.152: v2(110.47,78.42) 110.47,80.56 111.5,81.58 113.28,81.58 114.22,80.64 122.98,80.64 125.57,78.05 126.49,78.05 127.35,78.92 127.35,89.99 125.27,92.08 119.87,92.08 v2(118.6,90.81)
  BOTTOM w0.152: v2(110.47,78.42) 106.98,74.93 106.98,73.67 103.93,70.62 103.93,51.82 102.41,50.29 92.88,50.29 v2(92.38,49.78)
SOC_UART4_TXD: length 73.2
  TOP w0.152: R280.1 v2(125.01,91.53) ; U43.L26 v2(94.92,49.78)
  ART03 w0.152: v2(125.01,91.53) 126.69,89.85 v2(126.69,79.12)
  BOTTOM w0.152: v2(94.92,49.78) 102.66,49.78 104.44,51.56 104.44,70.33 107.57,73.46 107.57,74.68 112.01,79.12 v2(126.69,79.12)
SOC_USB0_DM: length 53.1
  TOP w0.155: v2(50.12,42.42) 49.96,42.58 49.96,46.83 52.8,49.67 63.69,49.67 64.02,49.33 U43.41 ; L9.1 56.19,14.6 56.19,15.58 v2(56.36,15.74)
  ART03 w0.137: v2(50.12,42.42) 49.96,42.25 49.96,34.88 53.77,31.07 53.77,23.1 53.95,22.93 53.95,22.55 53.77,22.38 53.77,22.01 53.95,21.83 53.95,21.46 53.77,21.28 53.77,20.91 53.95,20.73 53.95,20.36 53.77,20.18 53.77,18.88 53.95,18.7 53.95,18.33 53.77,18.15 53.77,17.53 54.28,17.02 55.63,17.02 56.19,16.46 56.19,15.91 v2(56.36,15.74)
SOC_USB0_DP: length 53
  TOP w0.155: U43.40 64.02,50.33 63.69,50 52.66,50 49.63,46.97 49.63,42.58 v2(49.46,42.42) ; L9.4 55.86,14.6 55.86,15.58 v2(55.7,15.74)
  ART03 w0.137: v2(55.7,15.74) 55.86,15.91 55.86,16.32 55.49,16.69 54.15,16.69 53.44,17.4 53.44,30.93 49.63,34.74 49.63,42.25 v2(49.46,42.42)
SOC_USB0_DRVVBUS: length 117
  TOP w0.152: v2(100.55,87.71) 100.73,87.88 U43.L46 ; R317.2 v1(52.8,29.9)
  BOTTOM w0.152: v1(52.8,29.9) 53.51,30.62 53.51,38.23 56.23,40.94 56.23,49.1 58.62,51.49 58.62,59.92 55.37,63.17 55.37,75.87 52.12,79.12 49.55,79.12 48.46,80.21 48.46,81.03 49.73,82.3 61.9,82.3 67.36,87.76 70.66,87.76 71.55,86.87 99.72,86.87 v2(100.55,87.71)
SOC_USB1_DM: length 90.8
  TOP w0.155: U28.30 136,29.34 136.08,29.43 138.82,29.43 v2(138.98,29.26) ; U43.44 67.78,45.58 67.44,45.24 67.44,40.43 v2(67.61,40.26)
  ART03 w0.137: v2(138.98,29.26) 138.82,29.43 137.8,29.43 137.26,29.96 137.26,33.85 134.99,36.12 133.95,36.12 133.79,35.97 133.4,35.97 133.24,36.12 132.85,36.12 132.7,35.97 132.3,35.97 132.15,36.12 131.75,36.12 131.6,35.97 131.21,35.97 131.05,36.12 130.66,36.12 130.5,35.97 130.11,35.97 129.95,36.12 120.32,36.12 119.44,35.23 112.69,35.23 111.67,36.25 101,36.25 99.91,37.34 96.95,37.34 96.37,37.92 96.37,38.22 96.05,38.53 82.84,38.53 81.15,40.22 71.19,40.22 70.57,40.85 67.58,40.85 67.44,40.71 67.44,40.43 v2(67.61,40.26)
SOC_USB1_DP: length 90.9
  TOP w0.155: U28.31 136,29.84 136.08,29.76 138.82,29.76 v2(138.98,29.92) ; v2(66.95,40.26) 67.12,40.43 67.12,45.24 66.78,45.58 U43.43
  ART03 w0.137: v2(138.98,29.92) 138.82,29.76 137.93,29.76 137.59,30.1 137.59,33.99 135.12,36.45 120.19,36.45 119.3,35.56 112.82,35.56 111.81,36.58 101.14,36.58 100.05,37.67 97.08,37.67 96.69,38.06 96.69,38.35 96.19,38.86 82.98,38.86 81.29,40.55 71.33,40.55 70.71,41.17 67.44,41.17 67.12,40.84 67.12,40.43 v2(66.95,40.26)
SOC_USB1_DRVVBUS: length 55.5
  TOP w0.152: v2(133.08,81.03) R274.1 ; U43.L49 v2(92.88,87.88)
  BOTTOM w0.152: v2(92.88,87.88) 94.64,87.88 94.97,87.55 99.23,87.55 100.33,88.65 103.4,88.65 105.94,86.11 116.1,86.11 120.49,81.71 132.39,81.71 v2(133.08,81.03)
SOC_VOUT0_DATA0: length 73.6
  TOP w0.152: R163.1 v2(140,27.43) ; U43.95 v2(108.76,60.33)
  BOTTOM w0.152: v2(140,27.43) 138.81,27.43 138.48,27.76 138.48,31.55 139.49,32.56 139.49,33.91 140,34.42 140,39.12 136.7,42.42 133.27,42.42 130.91,44.78 130.91,48.13 129.84,49.2 129.84,52.12 129.23,52.73 127.81,52.73 127.05,53.49 127.05,58.78 126.01,59.82 124.52,59.82 124.37,59.66 124.37,59.08 124.22,58.93 123.91,58.93 123.76,59.08 123.76,59.66 123.61,59.82 123.3,59.82 123.15,59.66 123.15,59.08 123,58.93 122.69,58.93 122.54,59.08 122.54,59.66 122.39,59.82 122.08,59.82 121.93,59.66 121.93,59.08 121.78,58.93 121.47,58.93 121.32,59.08 121.32,59.66 121.17,59.82 120.86,59.82 120.71,59.66 120.71,59.08 120.56,58.93 120.25,58.93 120.1,59.08 120.1,59.66 119.95,59.82 119.64,59.82 119.49,59.66 119.49,59.08 118.81,58.39 115.08,58.39 113.66,59.82 112.29,59.82 111.58,60.53 111.58,62.36 111.15,62.79 109.27,62.79 108.76,62.28 v2(108.76,60.33)
SOC_VOUT0_DATA1: length 75.7
  TOP w0.152: U43.107 v2(108.97,72.33) ; R164.1 v2(140,28.32)
  BOTTOM w0.152: v2(108.97,72.33) 110.87,72.33 114.37,68.83 118.39,68.83 118.82,68.4 118.82,66.98 119.27,66.52 124.74,66.52 125.65,65.61 125.65,64.03 126.39,63.3 128.24,63.3 132.13,59.41 132.13,57 131.49,56.36 131.49,55.6 133.17,53.92 133.17,50.93 134.51,49.58 134.51,45.85 134.9,45.47 137.97,45.47 142.92,40.51 142.92,28.75 142.49,28.32 142.26,28.32 142.11,28.17 142.11,26.8 141.96,26.64 141.65,26.64 141.5,26.8 141.5,28.17 141.35,28.32 v2(140,28.32)
SOC_VOUT0_DATA2: length 75.7
  TOP w0.152: U43.101 110.62,66.33 v2(114.73,62.23) ; R165.1 v2(140,29.21)
  BOTTOM w0.152: v2(140,29.21) 141.98,31.19 141.98,40.03 137.46,44.55 134.44,44.55 133.42,45.57 133.42,49.02 132.1,50.34 132.1,53.04 129.89,55.24 129.31,55.24 129,55.55 129,56.41 129.36,56.77 130.07,56.77 130.86,57.56 130.86,59.31 128.06,62.1 125.9,62.1 124.46,63.55 124.46,64.85 123.92,65.38 123.15,65.38 122.99,65.23 122.99,64.34 122.84,64.19 122.54,64.19 122.38,64.34 122.38,65.23 122.23,65.38 121.93,65.38 121.78,65.23 121.78,64.34 121.62,64.19 121.32,64.19 121.17,64.34 121.17,65.23 121.01,65.38 120.71,65.38 120.56,65.23 120.56,64.34 120.4,64.19 120.1,64.19 119.95,64.34 119.95,65.23 119.79,65.38 117.88,65.38 v2(114.73,62.23)
SOC_VOUT0_DATA3: length 73.9
  TOP w0.152: R166.1 v2(140,30.1) ; U43.106 v2(108.97,71.33)
  BOTTOM w0.152: v2(108.97,71.33) 108.97,70.92 109.13,70.76 109.69,70.76 109.85,70.92 109.85,71.6 110.02,71.78 110.3,71.78 110.45,71.63 110.45,70.92 110.61,70.76 111.65,70.76 114.09,68.33 117.88,68.33 118.36,67.84 118.36,66.67 119.1,65.94 124.51,65.94 125.09,65.35 125.09,63.86 126.18,62.76 128.06,62.76 131.57,59.26 131.57,57.51 130.37,56.31 130.37,55.47 132.58,53.26 132.58,50.6 133.88,49.3 133.88,45.82 134.69,45.01 137.61,45.01 142.52,40.11 142.52,30.94 140.31,28.73 139.75,28.73 139.49,28.98 139.49,29.59 v2(140,30.1)
SOC_VOUT0_DATA4: length 76.7
  TOP w0.152: R167.1 v2(140,30.99) ; v2(113.2,61.47) 113.2,62.66 111.53,64.33 U43.99
  BOTTOM w0.152: v2(140,30.99) 141.45,32.44 141.45,39.95 137.46,43.94 134.26,43.94 132.76,45.44 132.76,48.82 131.62,49.96 131.62,52.76 129.79,54.58 128.9,54.58 128.52,54.97 128.52,56.59 129.1,57.18 129.94,57.18 130.43,57.66 130.43,59.05 128.01,61.47 125.4,61.47 124.35,62.51 123.82,62.51 123.66,62.66 123.66,63.5 123.51,63.65 123.21,63.65 123.05,63.5 123.05,62.66 122.9,62.51 122.6,62.51 122.45,62.66 122.45,63.5 122.29,63.65 121.99,63.65 121.84,63.5 121.84,62.66 121.68,62.51 121.38,62.51 121.23,62.66 121.23,63.5 121.07,63.65 120.77,63.65 120.62,63.5 120.62,62.66 120.46,62.51 120.12,62.51 119.97,62.66 119.97,63.47 119.82,63.63 119.51,63.63 119.36,63.47 119.36,62.66 119.21,62.51 118.77,62.51 118.61,62.66 118.61,63.6 118.46,63.75 118.16,63.75 118,63.6 118,62.66 117.85,62.51 117.55,62.51 117.39,62.66 117.39,63.6 117.24,63.75 116.94,63.75 116.78,63.6 116.78,62.66 116.63,62.51 116,62.51 114.96,61.47 v2(113.2,61.47)
SOC_VOUT0_DATA5: length 77.1
  TOP w0.152: U43.105 v2(108.97,70.33) ; R168.1 v2(140,31.88)
  BOTTOM w0.152: v2(108.97,70.33) 111.25,70.33 112.62,68.96 112.62,68.01 112.77,67.86 113.69,67.86 113.84,67.7 113.84,67.4 113.69,67.25 112.77,67.25 112.62,67.09 112.62,66.79 112.77,66.64 113.69,66.64 113.84,66.48 113.84,66.18 113.69,66.03 112.77,66.03 112.62,65.87 112.62,65.57 112.77,65.42 113.69,65.42 113.84,65.27 113.84,64.96 113.69,64.81 112.77,64.81 112.62,64.66 112.62,64.35 112.77,64.2 113.69,64.2 113.84,64.05 113.84,63.74 113.69,63.59 112.77,63.59 112.62,63.44 112.62,63.13 112.77,62.98 113.69,62.98 113.84,62.83 113.84,62.52 113.69,62.37 112.77,62.37 112.62,62.22 112.62,61.34 113.11,60.85 115.06,60.85 115.98,61.77 124.33,61.77 125.25,60.85 126.72,60.85 127.99,59.59 127.99,54.38 128.55,53.82 129.66,53.82 130.91,52.58 130.91,49.86 132.15,48.62 132.15,45.21 133.93,43.43 137.21,43.43 141.02,39.62 141.02,32.89 v2(140,31.88)
SOC_VOUT0_DATA6: length 73.6
  TOP w0.152: U43.92 v2(113.33,57.33) ; R169.1 v2(138.86,32.77)
  BOTTOM w0.152: v2(138.86,32.77) 138.86,36.42 138.71,36.57 138.27,36.57 138.12,36.73 138.12,37.03 138.27,37.18 138.71,37.18 138.86,37.34 138.86,37.54 138.71,37.69 138.07,37.69 137.92,37.84 137.92,38.15 138.07,38.3 138.71,38.3 138.86,38.45 138.86,38.86 138.46,39.26 138.25,39.26 138.01,39.01 137.79,39.01 137.58,39.23 137.58,39.44 137.82,39.69 137.82,39.9 136.32,41.4 132.63,41.4 129.69,44.35 129.69,47.75 128.7,48.74 128.7,51.54 128.55,51.69 126.11,51.69 125.78,52.02 125.78,52.4 125.6,52.58 121.76,52.58 121.61,52.73 121.61,53.04 121.76,53.19 125.62,53.19 125.78,53.34 125.78,53.62 125.6,53.8 121.76,53.8 121.61,53.95 121.61,54.26 121.76,54.41 125.62,54.41 125.78,54.56 125.78,54.94 125.55,55.17 125.35,55.17 125.2,55.32 125.2,55.85 125.05,56.01 124.74,56.01 124.59,55.85 124.59,55.32 124.44,55.17 121.33,55.17 121.13,55.37 121.13,56.03 120.87,56.29 118.64,56.29 118.49,56.44 118.49,57.07 118.23,57.33 v2(113.33,57.33)
SOC_VOUT0_DATA7: length 75.3
  TOP w0.152: R170.1 v2(140,33.66) ; U43.98 v2(108.97,63.33)
  BOTTOM w0.152: v2(140,33.66) 140.51,34.16 140.51,39.37 136.95,42.93 133.68,42.93 131.54,45.06 131.54,48.36 130.37,49.53 130.37,52.35 129.43,53.29 128.14,53.29 127.53,53.9 127.53,59.18 126.39,60.33 123.08,60.33 122.93,60.48 122.93,61.04 122.78,61.19 122.47,61.19 122.32,61.04 122.32,60.48 122.17,60.33 121.86,60.33 121.71,60.48 121.71,61.04 121.56,61.19 121.25,61.19 121.1,61.04 121.1,60.48 120.95,60.33 120.64,60.33 120.49,60.48 120.49,61.04 120.34,61.19 120.04,61.19 119.88,61.04 119.88,60.48 119.73,60.33 119.1,60.33 118.97,60.2 118.97,59.36 118.49,58.88 115.34,58.88 113.89,60.33 112.77,60.33 112.04,61.06 112.04,67.51 111.88,67.67 111.38,67.67 111.2,67.49 111.2,67.06 111.04,66.91 110.21,66.91 110.05,66.75 110.05,66.45 110.21,66.3 111.04,66.3 111.2,66.14 111.2,65.84 111.04,65.69 110.21,65.69 110.05,65.53 110.05,65.23 110.21,65.08 111.04,65.08 111.2,64.92 111.2,63.58 110.96,63.33 v2(108.97,63.33)
SOC_VOUT0_DATA8: length 73.7
  TOP w0.152: R171.1 v2(139.37,34.54) ; U43.93 112.91,58.33 v2(113.33,57.91)
  BOTTOM w0.152: v2(139.37,34.54) 139.37,38.92 136.37,41.91 132.91,41.91 130.27,44.55 130.27,48.06 129.16,49.17 129.16,51.87 128.8,52.22 127.17,52.22 126.28,53.11 126.28,56.92 125.9,57.3 124.97,57.3 124.82,57.15 124.82,56.67 124.67,56.52 124.36,56.52 124.21,56.67 124.21,57.15 124.06,57.3 123.75,57.3 123.6,57.15 123.6,56.67 123.45,56.52 122.02,56.52 121.66,56.87 121.66,58.37 121.51,58.52 121.1,58.52 120.94,58.37 120.94,56.97 120.79,56.82 120.49,56.82 120.33,56.97 120.33,58.37 120.18,58.52 119.88,58.52 119.72,58.37 119.72,56.97 119.57,56.82 119.27,56.82 119.11,56.97 119.11,57.71 118.96,57.86 114.8,57.86 113.43,59.23 111.4,59.23 110.97,59.66 110.97,61.37 110.71,61.62 109.52,61.62 109.37,61.47 109.37,58.39 109.52,58.24 113,58.24 v2(113.33,57.91)
SOC_VOUT0_DATA9: length 75
  TOP w0.152: v2(106.6,53.34) 104.06,50.8 103.55,50.8 102.54,49.78 U43.L29 ; R172.1 v2(137.71,36.32)
  BOTTOM w0.152: v2(106.6,53.34) 108.12,53.34 110.66,55.88 116.61,55.88 117.09,55.4 119.17,55.4 120.48,54.09 120.48,51.78 120.75,51.51 124.35,51.51 125.27,50.6 127.38,50.6 127.58,50.39 127.58,48.69 127.43,48.54 126.51,48.54 126.36,48.39 126.36,48.08 126.51,47.93 127.43,47.93 127.58,47.78 127.58,44.91 132.1,40.39 135.68,40.39 136.15,39.92 136.15,39.2 136.31,39.05 137.05,39.05 137.21,38.9 137.21,38.59 137.05,38.44 135.16,38.44 135.01,38.29 135.01,37.98 135.16,37.83 137.05,37.83 137.21,37.68 137.21,37.37 137.05,37.22 136.31,37.22 136.15,37.07 136.15,36.55 136,36.4 135.2,36.4 135.05,36.24 135.05,35.94 135.2,35.79 136,35.79 136.15,35.63 136.15,35.33 136,35.18 135.2,35.18 135.05,35.02 135.05,34.72 135.2,34.57 136,34.57 136.15,34.41 136.15,33.74 136.47,33.43 137.13,33.43 137.38,33.68 137.38,34.72 137.54,34.88 138.27,34.88 138.43,35.03 138.43,35.33 138.27,35.49 137.54,35.49 137.38,35.64 137.38,35.99 v2(137.71,36.32)
SOC_VOUT0_DATA10: length 73.3
  TOP w0.152: U43.117 108.85,82.33 114.98,76.2 v2(115.24,76.2) ; v2(135.11,45.91) 135.11,38.65 135.53,38.23 139.69,38.23 R173.1
  BOTTOM w0.152: v2(115.24,76.2) 113.84,74.8 113.84,70.1 114.63,69.32 117.05,69.32 117.21,69.47 117.21,71.02 117.36,71.17 117.66,71.17 117.82,71.02 117.82,69.47 117.97,69.32 119.17,69.32 119.4,69.09 119.4,67.31 119.55,67.16 125.19,67.16 126.08,66.27 126.08,64.87 126.39,64.57 127.86,64.57 132.94,59.49 132.94,56.85 133.73,56.06 133.73,51.44 135.11,50.05 v2(135.11,45.91)
SOC_VOUT0_DATA11: length 77.3
  TOP w0.152: U43.L27 96.57,49.78 97.96,48.39 104.69,48.39 v2(105.2,48.9) ; R174.1 143,39.05 142.85,39.2 142.85,41.12 142.69,41.27 142.39,41.27 142.24,41.12 142.24,39.23 142.06,39.05 141.78,39.05 141.63,39.2 141.63,41.12 141.47,41.27 141.17,41.27 141.02,41.12 141.02,39.23 140.84,39.05 140.56,39.05 140.41,39.2 140.41,41.12 140.26,41.27 139.95,41.27 139.8,41.12 139.8,39.23 139.62,39.05 139.34,39.05 139.19,39.2 139.19,41.12 139.04,41.27 138.73,41.27 138.58,41.12 138.58,39.23 138.4,39.05 v2(135.68,39.05)
  BOTTOM w0.152: v2(135.68,39.05) 131.92,39.05 126.16,44.81 126.16,46.86 125.37,47.65 125.37,49.5 125.09,49.78 124.56,49.78 123.8,50.55 120.14,50.55 119.53,51.16 119.53,53.7 118.93,54.29 116.39,54.29 115.82,54.86 111.17,54.86 v2(105.2,48.9)
